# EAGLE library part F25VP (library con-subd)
SUB-D
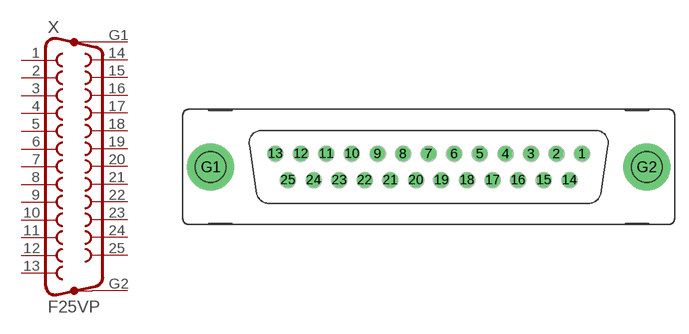
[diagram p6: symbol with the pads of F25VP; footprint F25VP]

Designator prefix X

## F25VP (OC_FARNELL: unknown; OC_NEWARK: unknown)  [F25VP]
1  1  pas
2  2  pas
3  3  pas
4  4  pas
5  5  pas
6  6  pas
7  7  pas
8  8  pas
9  9  pas
10  10  pas
11  11  pas
12  12  pas
13  13  pas
14  14  pas
15  15  pas
16  16  pas
17  17  pas
18  18  pas
19  19  pas
20  20  pas
21  21  pas
22  22  pas
23  23  pas
24  24  pas
25  25  pas
G1  G1  pas
G2  G2  pas

## Footprint F25VP (pad centres in mm)
SUB-D
drill 1.016 octagon: 1 16.561,1.422; 2 13.792,1.422; 3 11.049,1.422; 4 8.28,1.422; 5 5.512,1.422; 6 2.769,1.422; 7 0,1.422; 8 -2.769,1.422; 9 -5.512,1.422; 10 -8.28,1.422; 11 -11.049,1.422; 12 -13.792,1.422; 13 -16.561,1.422; 14 15.189,-1.422; 15 12.421,-1.422; 16 9.652,-1.422; 17 6.909,-1.422; 18 4.14,-1.422; 19 1.372,-1.422; 20 -1.372,-1.422; 21 -4.14,-1.422; 22 -6.909,-1.422; 23 -9.652,-1.422; 24 -12.421,-1.422; 25 -15.189,-1.422
drill 3.302 pad 5.08 round: G1 -23.52,0; G2 23.52,0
